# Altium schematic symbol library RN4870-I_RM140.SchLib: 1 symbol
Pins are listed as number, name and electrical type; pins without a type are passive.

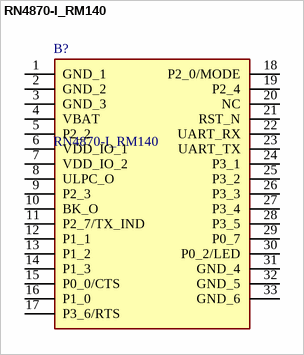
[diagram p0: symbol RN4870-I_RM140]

## RN4870-I_RM140
designator B?
Bluetooth Modules (802.15.1) Bluetooth Low Energy BLE Module, Shielded, Antenna, ASCII Interface, 12x22mm; Manufacturer_Name: Microchip; Manufacturer_Part_Number: RN4870-I/RM140; Geometry.Height: 2.46mm
footprint RN4870IRM140
pins: 1 GND_1, 2 GND_2, 3 GND_3, 4 VBAT, 5 P2_2, 6 VDD_IO_1, 7 VDD_IO_2, 8 ULPC_O, 9 P2_3, 10 BK_O, 11 P2_7/TX_IND, 12 P1_1, 13 P1_2, 14 P1_3, 15 P0_0/CTS, 16 P1_0, 17 P3_6/RTS, 18 P2_0/MODE, 19 P2_4, 20 NC, 21 RST_N, 22 UART_RX, 23 UART_TX, 24 P3_1, 25 P3_2, 26 P3_3, 27 P3_4, 28 P3_5, 29 P0_7, 30 P0_2/LED, 31 GND_4, 32 GND_5, 33 GND_6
